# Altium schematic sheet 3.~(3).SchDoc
size 420 x 297 mm
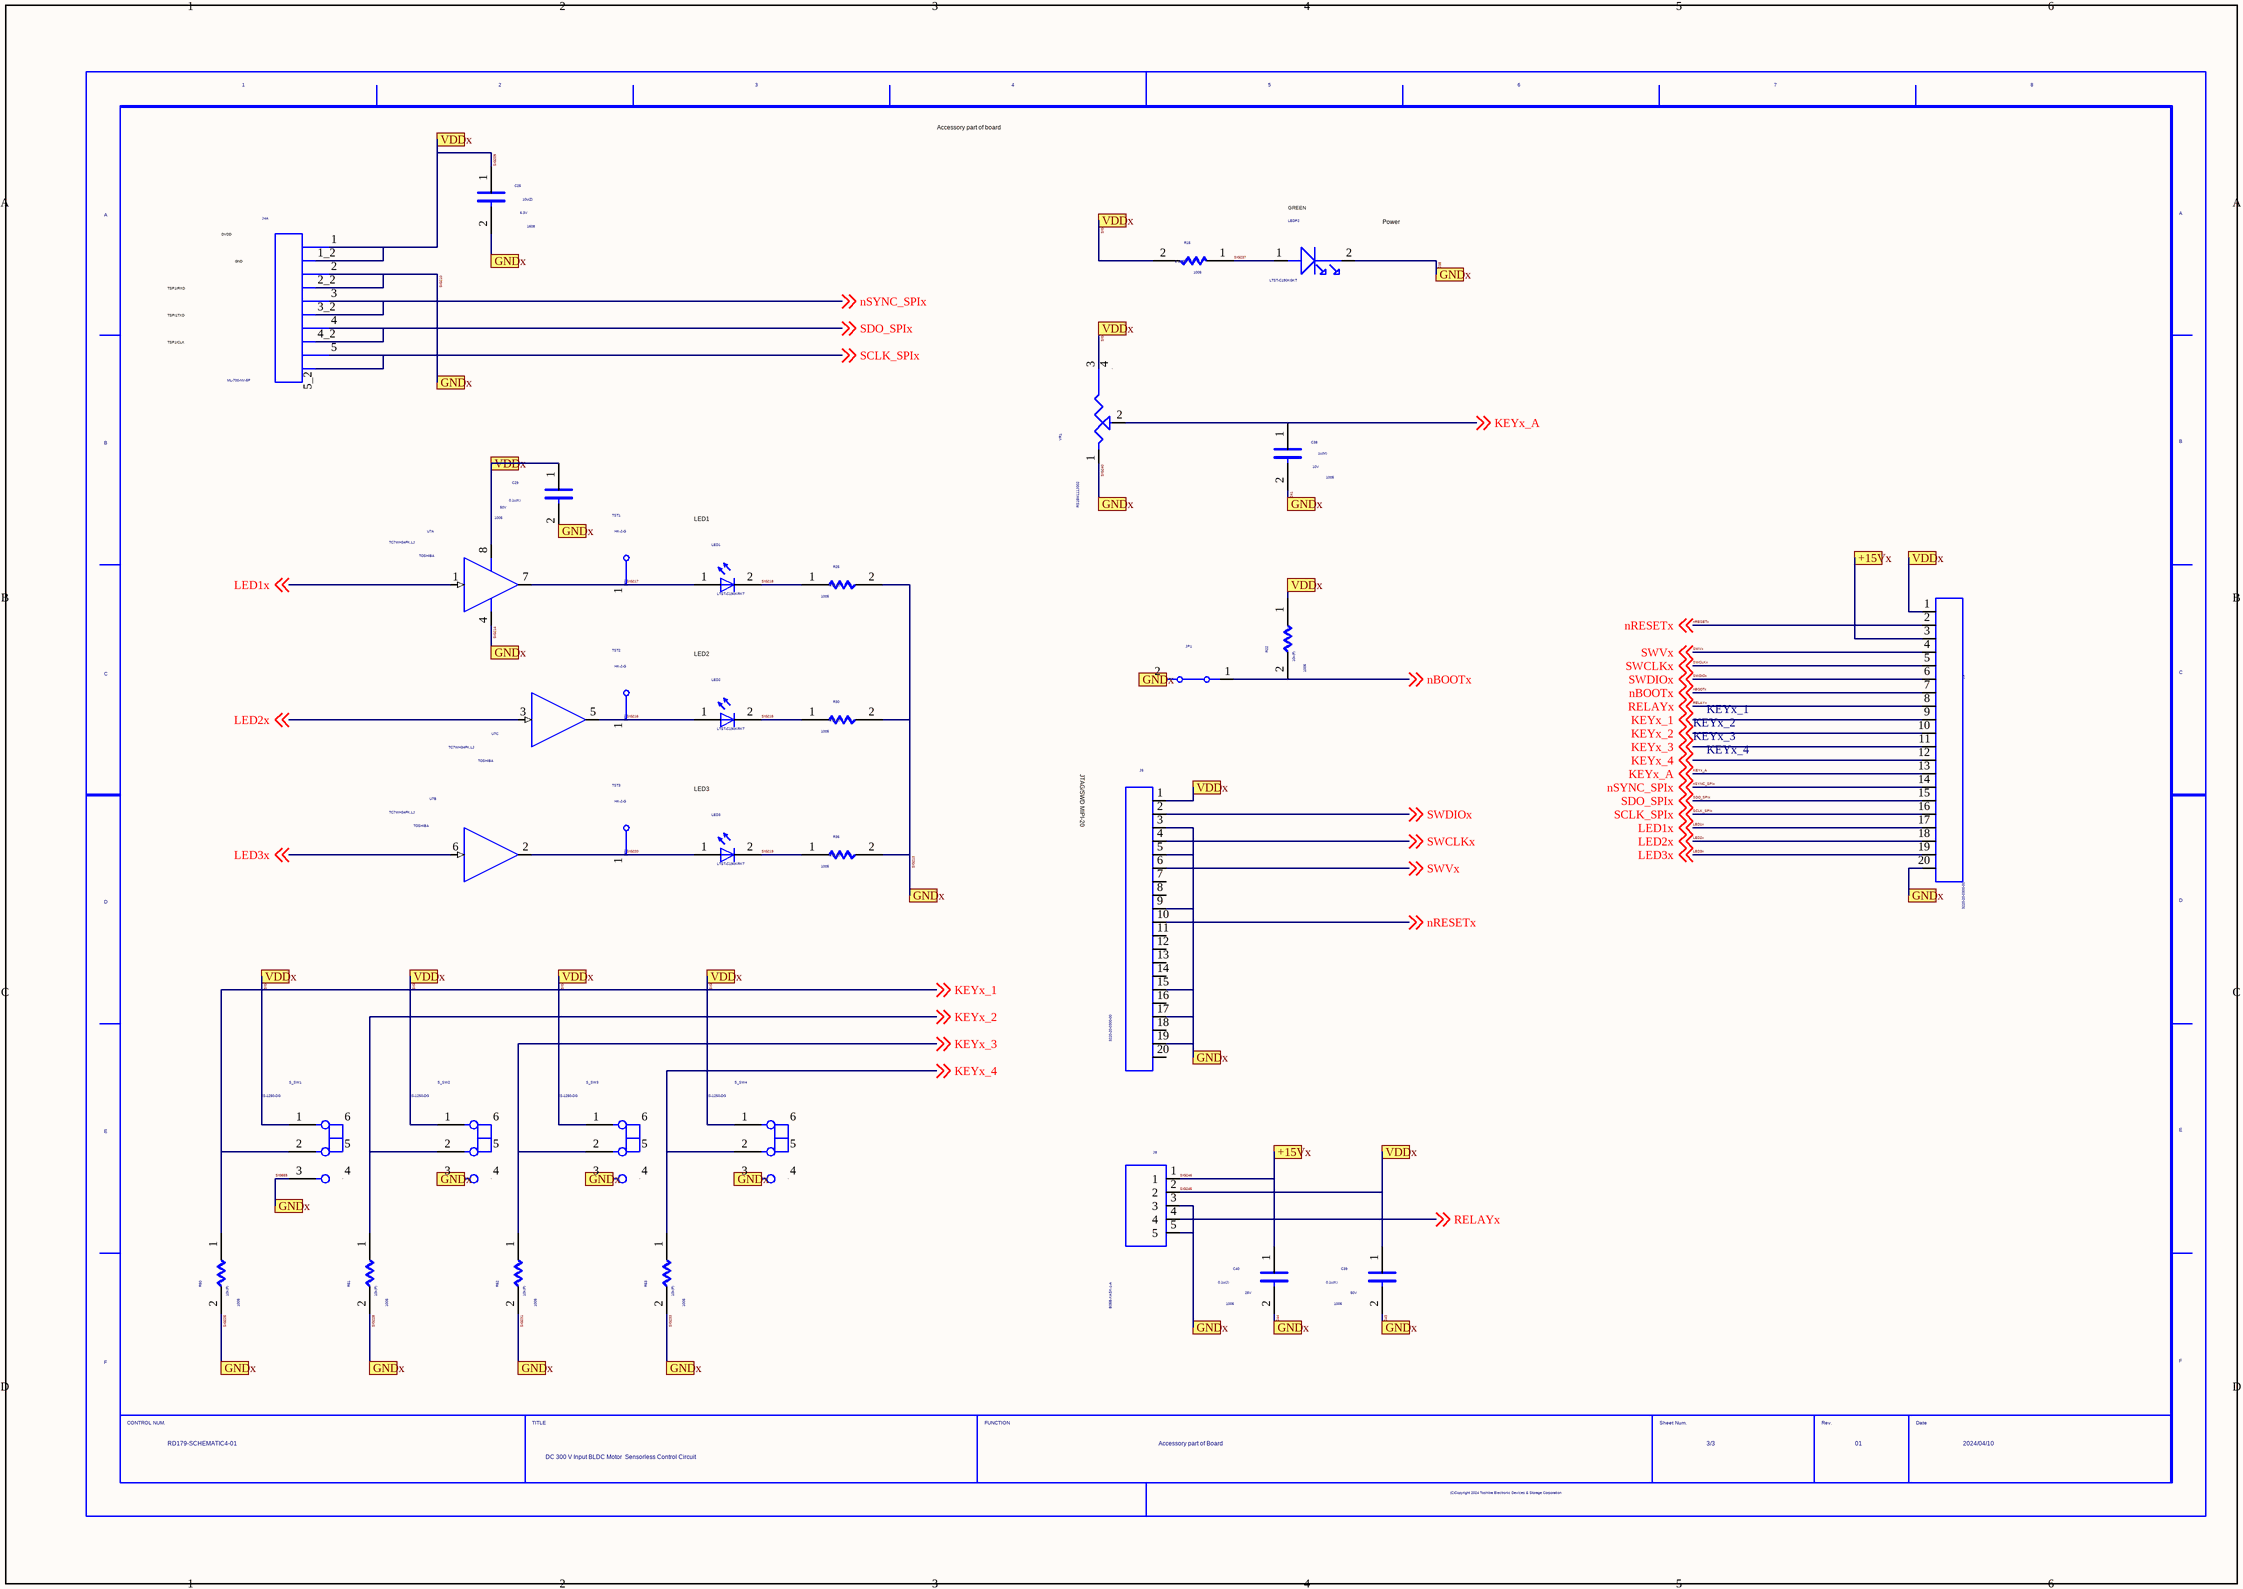
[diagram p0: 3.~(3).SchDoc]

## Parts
C25  SIZECODESMD: 1608  VAL2: 6.3V  VAL1: 10u(Z)  (hidden comment: C)
C29  SIZECODESMD: 1005  VAL2: 50V  VAL1: 0.1u(K)  (hidden comment: C)
C38  SIZECODESMD: 1005  VAL2: 10V  VAL1: 1u(M)  (hidden comment: C)
C39  SIZECODESMD: 1005  VAL2: 50V  VAL1: 0.1u(K)  (hidden comment: C)
C40  SIZECODESMD: 1005  VAL2: 25V  VAL1: 0.1u(J)  (hidden comment: C)
J4  VAL3: ML-700-NV-5P  (hidden comment: ML_700_NH_5P)  (part A of 3)
J5  3220-20-0300-00
J8  B05B-XASK-1-A
J9  3220-20-0300-00
JP1  JP  (value not drawn)
LED1  VAL3: LTST-C190KRKT  (hidden comment: LED)
LED2  VAL3: LTST-C190KRKT  (hidden comment: LED)
LED3  VAL3: LTST-C190KRKT  (hidden comment: LED)
LEDP2  LTST-C190KGKT  [LED]
R15  SIZECODESMD: 1005  VAL1: 2.2k(F)  (hidden comment: R)
R22  SIZECODESMD: 1005  VAL1: 10k(F)  (hidden comment: R)
R25  SIZECODESMD: 1005  VAL1: 4.7k(F)  (hidden comment: R)
R30  SIZECODESMD: 1005  VAL1: 4.7k(F)  (hidden comment: R)
R36  SIZECODESMD: 1005  VAL1: 4.7k(F)  (hidden comment: R)
R50  SIZECODESMD: 1005  VAL1: 10k(F)  (hidden comment: R)
R51  SIZECODESMD: 1005  VAL1: 10k(F)  (hidden comment: R)
R52  SIZECODESMD: 1005  VAL1: 10k(F)  (hidden comment: R)
R53  SIZECODESMD: 1005  VAL1: 10k(F)  (hidden comment: R)
S_SW1  VAL3: IS-1250-DG  (hidden comment: SW_IS_1250)
S_SW2  VAL3: IS-1250-DG  (hidden comment: SW_IS_1250)
S_SW3  VAL3: IS-1250-DG  (hidden comment: SW_IS_1250)
S_SW4  VAL3: IS-1250-DG  (hidden comment: SW_IS_1250)
TST1  VAL3: HK-2-G  (hidden comment: TP)
TST2  VAL3: HK-2-G  (hidden comment: TP)
TST3  VAL3: HK-2-G  (hidden comment: TP)
U7  USERCOMPTEXT3: TOSHIBA  VAL3: TC7WH34FK,LJ  (hidden comment: SN74LVC3G17DCUR_1)  (parts A,B,C of 3)
U?  DATE: 2024/04/10  TITLE: DC 300 V Input BLDC Motor / Sensorless Control Circuit  DRAWINGNUMBER: RD179-SCHEMATIC4-01  FUNCTION: Accessory part of Board  SHEETNUMBER: 3/3  REVISION: 01  (hidden comment: WAKU_DEF100)
VR1  VAL3: RS15M111J002  (hidden comment: VR)

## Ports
+15Vx, GNDx, VDDx

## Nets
KEYx_1: J9.9 R50.1 S_SW1.2 ; off-sheet KEYx_1
KEYx_2: J9.10 R51.1 S_SW2.2 ; off-sheet KEYx_2
KEYx_3: J9.11 R52.1 S_SW3.2 ; off-sheet KEYx_3
KEYx_4: J9.12 R53.1 S_SW4.2 ; off-sheet KEYx_4
KEYx_A: C38.1 J9.13 VR1.2(WIPER) ; off-sheet KEYx_A
LED1x: J9.17 U7.1(INA) ; off-sheet LED1x
LED2x: J9.18 U7.3 ; off-sheet LED2x
LED3x: J9.19 U7.6 ; off-sheet LED3x
nBOOTx: J9.7 JP1.1 R22.2 ; off-sheet nBOOTx
nRESETx: J5.10 J9.2 ; off-sheet nRESETx
nSYNC_SPIx: J4.3 J4.3_2(3-2) J9.14 ; off-sheet nSYNC_SPIx
RELAYx: J8.4 J9.8 ; off-sheet RELAYx
SCLK_SPIx: J4.5 J4.5_2(5-2) J9.16 ; off-sheet SCLK_SPIx
SDO_SPIx: J4.4 J4.4_2(4-2) J9.15 ; off-sheet SDO_SPIx
SIG209: C25.1 C29.1 C39.1 J4.1 J4.1_2(1-2) J5.1 J8.2 J9.1 R15.2 R22.1 S_SW1.1 S_SW2.1 S_SW3.1 S_SW4.1 U7.8(+3.3) VR1.3(B) ; port VDDx  [also labelled SIG212, SIG223, SIG227, SIG230, SIG234, SIG236, SIG239, SIG245]
SIG210: C25.2 C29.2 C38.2 C39.2 C40.2 J4.2 J4.2_2(2-2) J5.3 J5.5 J5.9 J5.15 J5.17 J5.19 J8.3 J8.5 J9.20 JP1.2 LEDP2.2(Cathode) R25.2 R30.2 R36.2 R50.2 R51.2 R52.2 R53.2 S_SW1.3 S_SW2.3 S_SW3.3 S_SW4.3 U7.4(GND) VR1.1(A) ; port GNDx  [also labelled SIG213, SIG214, SIG225, SIG228, SIG231, SIG233, SIG238, SIG240, SIG241, SIG242, SIG243, SIG244, SIG555]
SIG215: LED2.2(C) R30.1
SIG216: LED2.1(A) TST2.1 U7.5
SIG217: LED1.1(A) TST1.1 U7.7(OUTY)
SIG218: LED1.2(C) R25.1
SIG219: LED3.2(C) R36.1
SIG220: LED3.1(A) TST3.1 U7.2
SIG237: LEDP2.1(Anode) R15.1
SIG246: C40.1 J8.1 J9.3 ; port +15Vx
SWCLKx: J5.4 J9.5 ; off-sheet SWCLKx
SWDIOx: J5.2 J9.6 ; off-sheet SWDIOx
SWVx: J5.6 J9.4 ; off-sheet SWVx

Not connected (* = marked no-connect by the designer): J5 7 8 11 12 13 14 16 18 20; S_SW1 4 5 6; S_SW2 4 5 6; S_SW3 4 5 6; S_SW4 4 5 6; VR1 4

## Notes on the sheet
- Accessory part of board
- DVDD
- GND
- (near LEDP2) GREEN
- (near LEDP2) Power
- TSPI1TXD
- TSP1IRXD
- TSP1ICLK
- LED1
- LED2
- KEYx_2
- KEYx_1
- LED3
- JTAG/SWD MIPI-20
- KEYx_3
- KEYx_4

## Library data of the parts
C25 = C: OriginalSymbolOrigin: (2540,7620); COMP: CRC-1608-DEF
C29 C38-C40 = C: OriginalSymbolOrigin: (2540,7620); COMP: CRC-1005-DEF
J4 = ML_700_NH_5P: COMP: ML-700-NV-5P_R00; TIME: 16:32:00; UPDATEUSER: t5459927; UPDATETIME: 14:23:35; SAVECOUNT: 6; SAVEAREA0: -56271,-34402,27424,4178; OriginalSymbolOrigin: (0,0)
J5 = CON20: COMP: 3220-20-0300-00_R00; TIME: 16:32:01; UPDATEUSER: t5459927; SAVECOUNT: 1; SAVEAREA0: -36272,-54408,42011,2984; OriginalSymbolOrigin: (0,0); INSTANCENAME: I16846450
J8 = B05B_XASK_1_A: COMP: B05B-XASK-1-A_R00; TIME: 16:31:59; UPDATEUSER: t5459927; SAVECOUNT: 1; SAVEAREA0: -8887,-15544,13478,852; OriginalSymbolOrigin: (0,0); INSTANCENAME: I16947079
J9 = CON20: COMP: 3220-20-0300-00_R00; TIME: 16:32:01; UPDATEUSER: t5459927; SAVECOUNT: 1; SAVEAREA0: -36272,-54408,42011,2984; OriginalSymbolOrigin: (0,0); INSTANCENAME: I17018983
JP1 = JP: OriginalSymbolOrigin: (2540,5080); VAL3: PH-1x40SG; COMP: PH-1X02SG_R00
LED1-LED3 = LED: SAVEAREA0: -6799,-183,19247,15664; TIME: 14:49:55; UPDATEUSER: fukuda-y; UPDATETIME: 13:54:07; SAVECOUNT: 4; OriginalSymbolOrigin: (5080,7620); COMP: LTST-C190_R00
LEDP2 = LED_3RED: COMP: LTST-C190_R00; TIME: 16:32:00; UPDATEUSER: t5459927; SAVECOUNT: 1; OriginalSymbolOrigin: (0,0); INSTANCENAME: I16847094
R15 R22 R50-R53 = R: OriginalSymbolOrigin: (5080,5080); VAL2: 100mW; COMP: CRC-1005-DEF
R25 R30 R36 = R: OriginalSymbolOrigin: (5080,5080); VAL2: 63mW; COMP: CRC-1005-DEF
S_SW1-S_SW4 = SW_IS_1250: COMP: IS-1250_R00; TIME: 16:32:00; UPDATEUSER: t5459927; UPDATETIME: 08:47:03; SAVECOUNT: 3; SAVEAREA0: -34974,-23415,45046,13471; OriginalSymbolOrigin: (-2540,0)
TST1-TST3 = TP: TIME: 16:12:21; UPDATEUSER: fukuda-y; UPDATETIME: 16:18:11; SAVECOUNT: 2; SAVEAREA0: -242,-92,12810,7836; OriginalSymbolOrigin: (0,7620)
U7 = SN74LVC3G17DCUR_1: COMP: TC7WH34FK; ORDER: 0; TIME: 16:32:01; UPDATEUSER: t5459927; UPDATETIME: 15:47:45; SAVECOUNT: 5; SAVEAREA0: -11904,-17167,21643,7427; OriginalSymbolOrigin: (0,0); CaptureCellPackProp: SN74LVC3G17DCUR_1A; FUNCN: TC7WH34FK_LJ_1
U? = WAKU_DEF100: PLOTTIME: HH:MM; SAVEAREA0: 147884,-66467,487065,89883; TIME: 14:30:25; UPDATEUSER: sptcae13; UPDATETIME: 09:35:02; SAVECOUNT: 7; OriginalSymbolOrigin: (10160,284480)
VR1 = VR: COMP: RS15M111J002_R00; TIME: 16:32:00; UPDATEUSER: t5459927; UPDATETIME: 09:39:06; SAVECOUNT: 2; SAVEAREA0: -14973,-11876,27253,11499; OriginalSymbolOrigin: (0,0)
